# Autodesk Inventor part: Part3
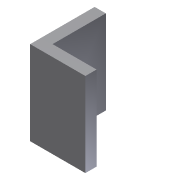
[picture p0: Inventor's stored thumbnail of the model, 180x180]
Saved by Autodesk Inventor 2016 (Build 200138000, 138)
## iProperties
Created: 2009-05
Part Number: Part3
Document SubType Name: Modeling
Designer: Sham
Density: 1 g/cm^3
Material: Generic
Appearance: Default
Author: Sham
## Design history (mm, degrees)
sketch "Sketch1"
  geometry: L1 (-20, 23)-(-20, 0); L2 (-20, 0)-(-0.309, 0); L3 (-0.309, 0)-(-0.309, 4); L4 (-0.309, 4)-(-16, 4); L5 (-16, 4)-(-16, 23); L6 (-16, 23)-(-20, 23)
  constraints: 12 end point, 5 perpendicular
extrude "Extrusion1" new body sketch "Sketch1" distance "d0" = 30; taper "d1" = 0 deg
body "Solid1"
